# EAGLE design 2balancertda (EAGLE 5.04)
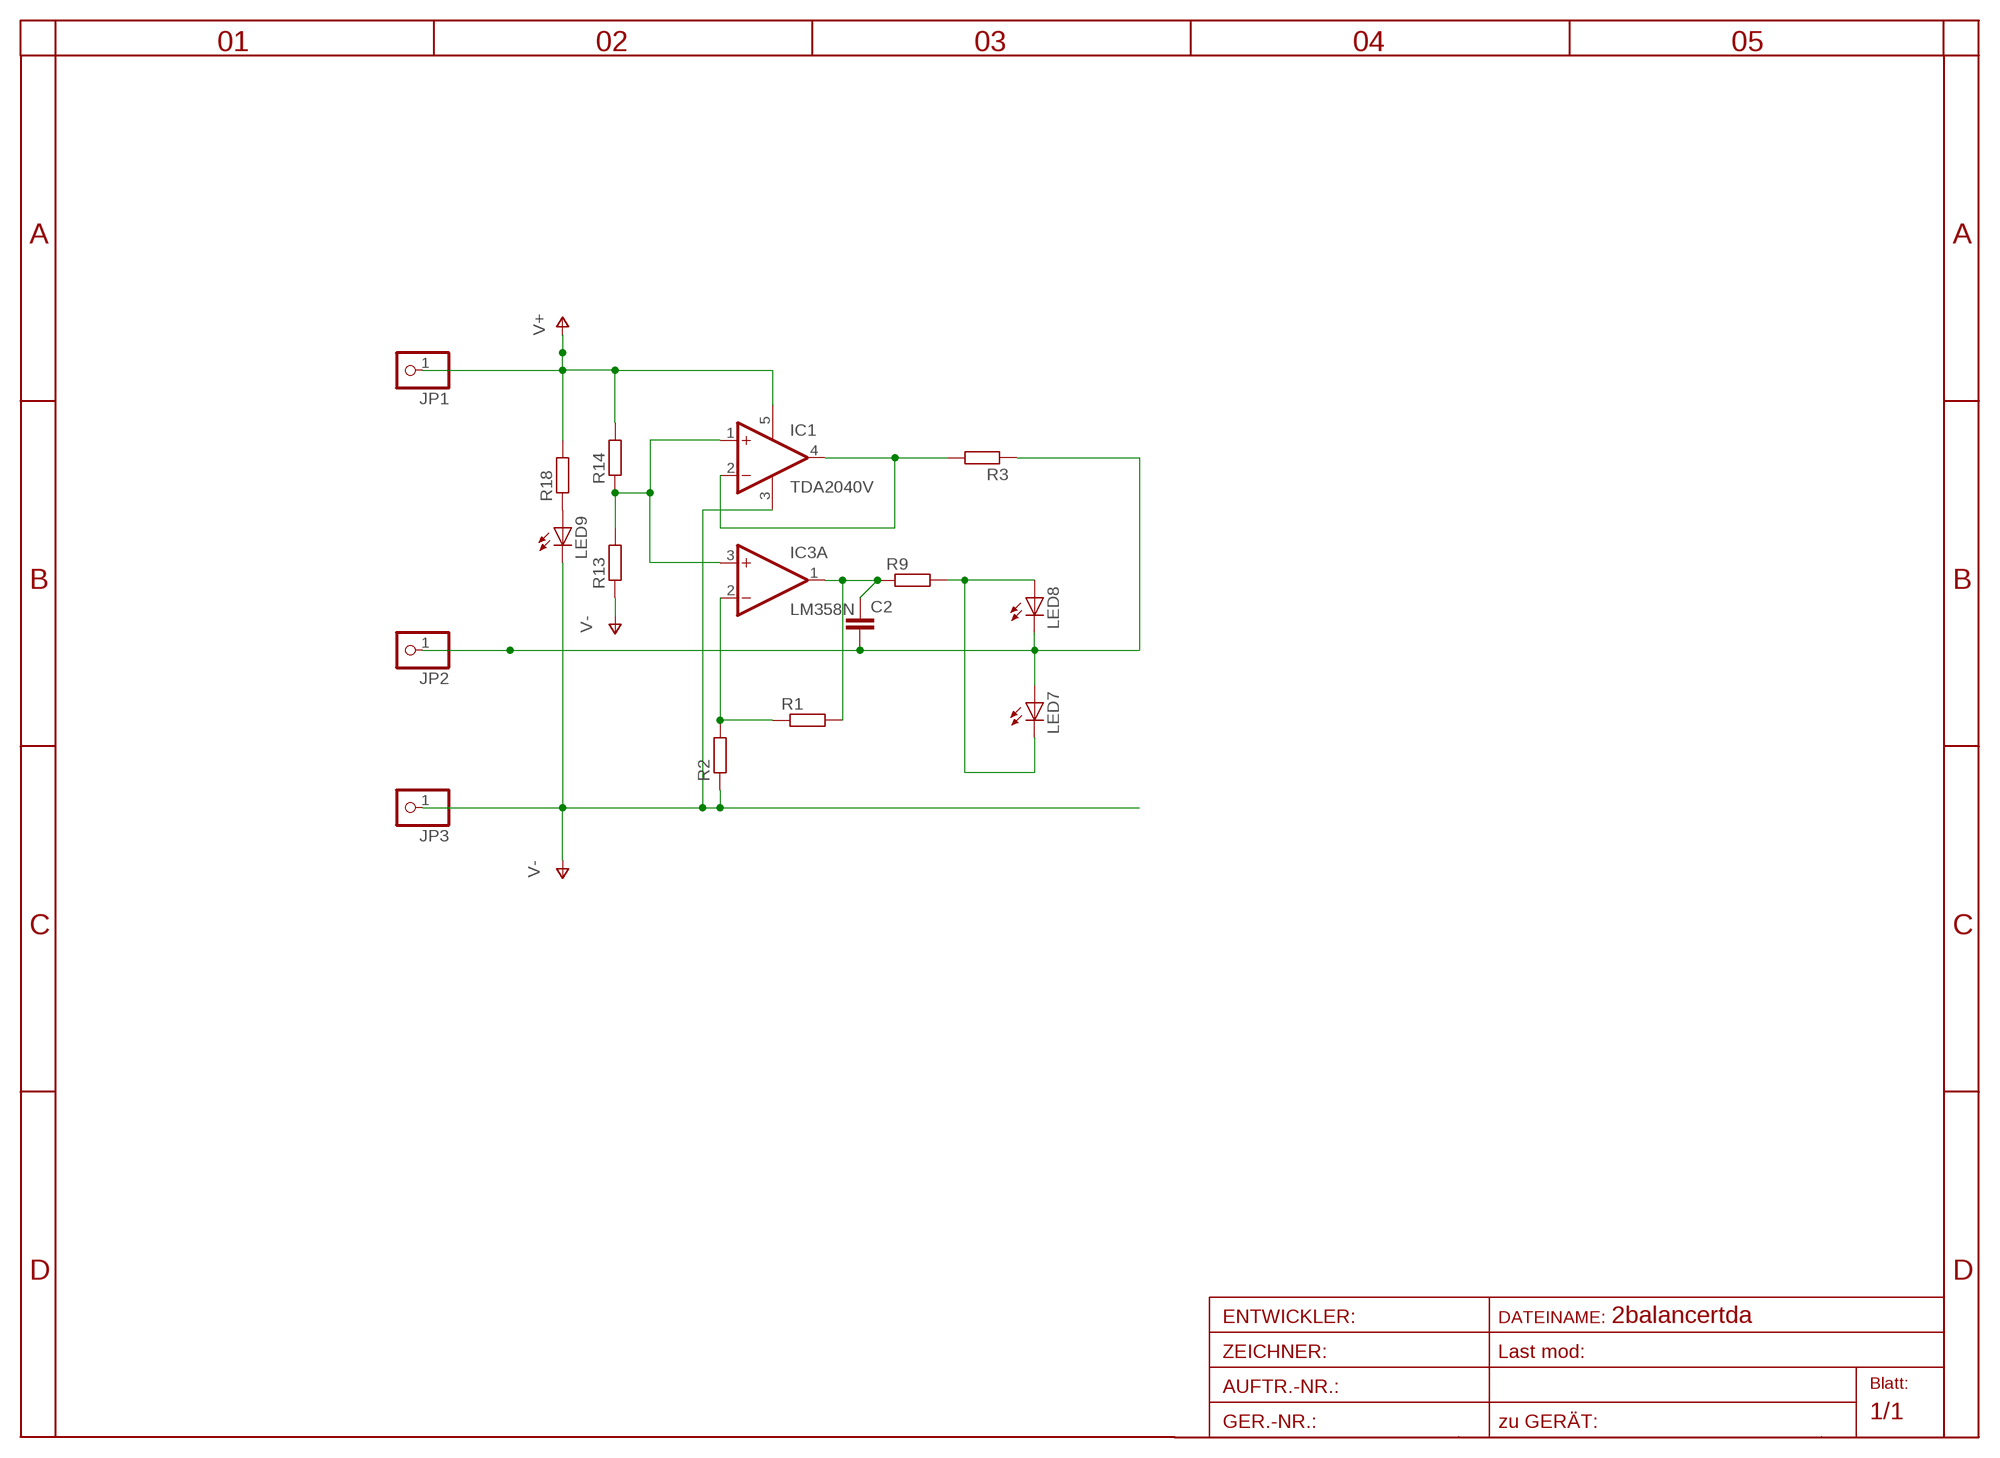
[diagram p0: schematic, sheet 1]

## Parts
C2  C-EU025-024X044  [C025-024X044]
IC1  TDA2040V  [CB360]
IC3  LM358N  [DIL08]
JP1  PINHD-1X1  [1X01]
JP2  PINHD-1X1  [1X01]
JP3  PINHD-1X1  [1X01]
LED7  LED3MM  [LED3MM]
LED8  LED3MM  [LED3MM]
LED9  LED3MM  [LED3MM]
R1  R-EU_0204/5  [0204/5]
R2  R-EU_0204/5  [0204/5]
R3  R-EU_0613/15  [P0613/15]
R9  R-EU_0204/5  [0204/5]
R13  R-EU_0204/5  [0204/5]
R14  R-EU_0204/5  [0204/5]
R18  R-EU_0204/5  [0204/5]

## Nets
B1: C2.2 JP2.1 LED7.A LED8.K(C) R3.1
N$1: IC3.2(A:-IN) R1.1 R2.2
N$2: IC1.2(-IN) IC1.4(OUT) R3.2
N$9: LED7.K(C) LED8.A R9.2
N$25: C2.1 IC3.1(A:OUT) R1.2 R9.1
N$28: IC1.1(+IN) IC3.3(A:+IN) R13.2 R14.1
N$34: LED9.A R18.1
V+: IC1.5(V+) JP1.1 R14.2 R18.2
V-: IC1.3(V-) JP3.1 LED9.K(C) R2.1 R13.1
Unconnected: IC3.5(B:+IN) IC3.6(B:-IN) IC3.7(B:OUT)

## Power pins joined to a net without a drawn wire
V+: IC3.8(P:V+)
V-: IC3.4(P:V-)

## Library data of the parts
C2 = rcl-2:C-EU: CAPACITOR, European symbol
IC1 = linear:TDA2040: Power OP AMP
IC3 = linear:LM358: OP AMP also LM158; LM258; LM2904 Source: http://cache.national.com/ds/LM/LM158.pdf
JP1-JP3 = pinhead:PINHD-1X1: PIN HEADER
LED7-LED9 = led:LED: LED
R1-R3 R9 R13 R14 R18 = rcl-2:R-EU_: RESISTOR, European symbol

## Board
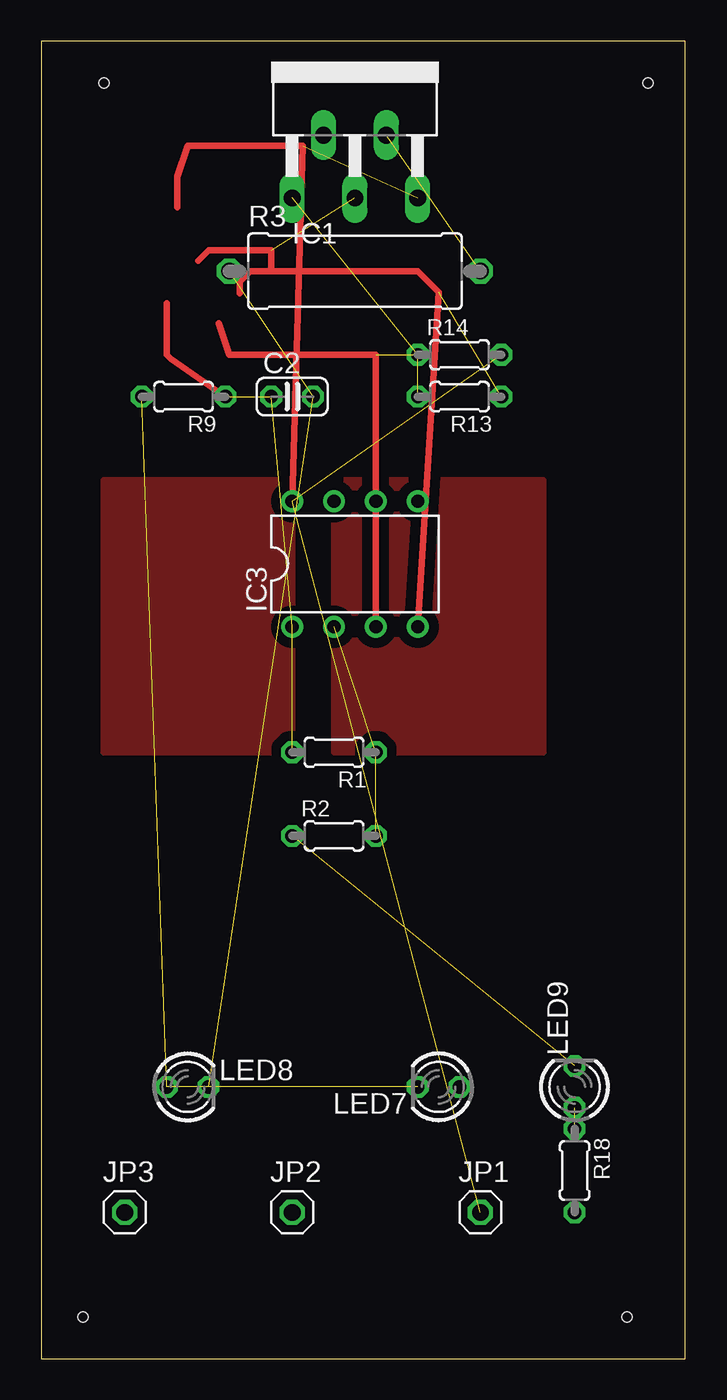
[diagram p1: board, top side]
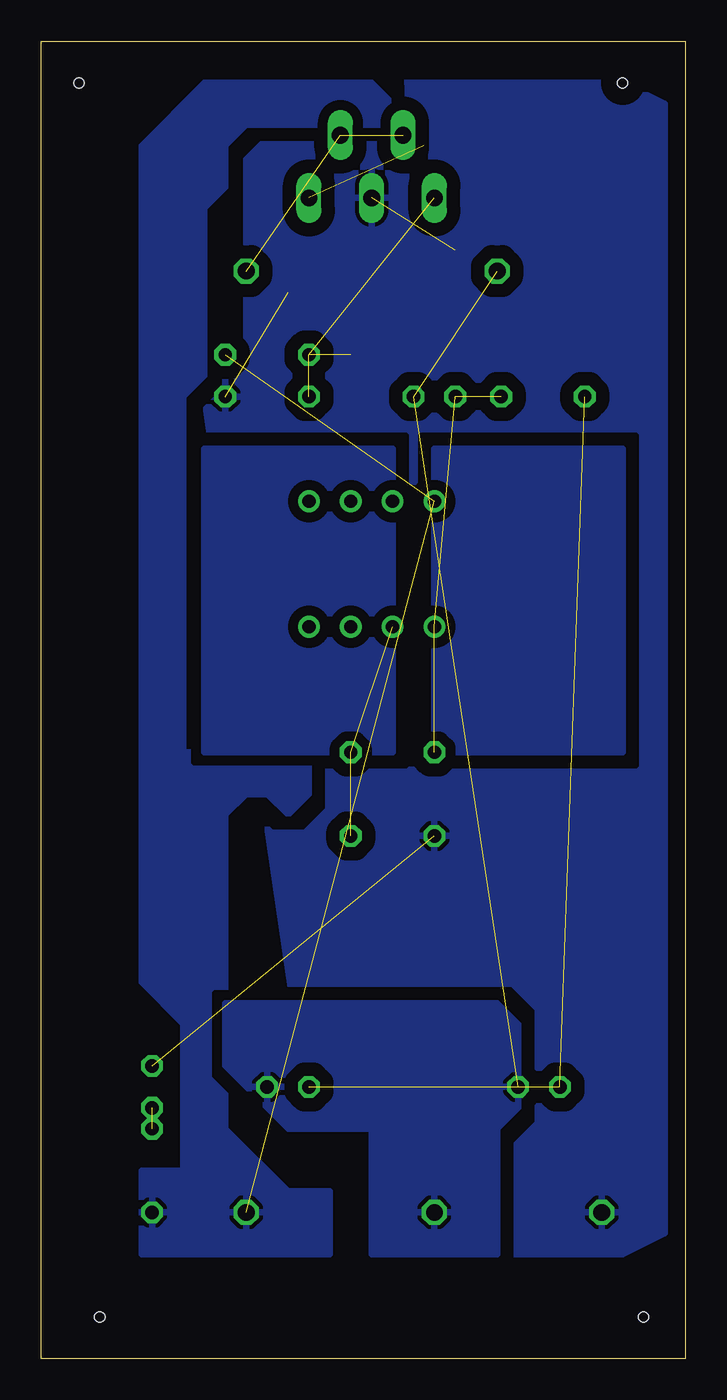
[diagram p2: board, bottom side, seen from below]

Size 39.12 x 80 mm. Coordinates in mm from the lower left corner, seen from the top.
Outline: 0,0 39.12,0 39.12,80 0,80 0,0
Copper layers (1*16): Top 0.035mm / dielectric 1.5mm / Bottom 0.035mm
Design rules "default": minimum track width 10mil, minimum drill 24mil, track to track 8mil, track to pad 8mil, pad to pad 8mil, via to via 8mil, smd to smd 8mil, copper to edge 40mil, drill to drill 8mil, minimum pad ring 10mil, minimum via ring 8mil, stop-mask expansion 4mil, vias tented up to drill 0mil, thermal gap 10mil
Holes 0.6 mm at 2.54,2.54 35.56,2.54 36.83,77.47 3.81,77.47

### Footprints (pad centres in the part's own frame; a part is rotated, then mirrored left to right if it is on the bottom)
C025-024X044 = drill 0.813 octagon: 1 -1.27,0; 2 1.27,0
CB360 = drill 1.016 long: 1 -3.81,-8.255; 2 -1.905,-4.445; 3 0,-8.255; 4 1.905,-4.445; 5 3.81,-8.255
DIL08 = drill 0.813 pad 1.27 round: 1 -3.81,-3.81; 2 -1.27,-3.81; 3 1.27,-3.81; 4 3.81,-3.81; 5 3.81,3.81; 6 1.27,3.81; 7 -1.27,3.81; 8 -3.81,3.81
1X01 = drill 1.016 octagon: 1 0,0
LED3MM = drill 0.813 octagon: A -1.27,0; K 1.27,0
0204/5 = drill 0.813 octagon: 1 -2.54,0; 2 2.54,0
P0613/15 = drill 1.016 octagon: 1 -7.62,0; 2 7.62,0

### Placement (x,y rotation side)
C2  15.24,58.42 0 top
IC1  19.05,78.74 0 top
IC3  19.05,48.26 0 top
JP1  26.67,8.89 0 top
JP2  15.24,8.89 0 top
JP3  5.08,8.89 0 top
LED7  24.13,16.51 180 top
LED8  8.89,16.51 0 top
LED9  32.38,16.51 90 top
R1  17.78,36.83 180 top
R2  17.78,31.75 0 top
R3  19.05,66.04 0 top
R9  8.65,58.42 180 top
R13  25.4,58.42 180 top
R14  25.4,60.96 0 top
R18  32.38,11.43 270 top

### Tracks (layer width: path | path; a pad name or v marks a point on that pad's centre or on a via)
B1  (2 unrouted)
  pour Bottom (isolate 0.813, rank 3): 11.43,6.35 11.43,13.97 10.16,15.24 10.16,20.32 11.43,21.59 27.94,21.59 27.94,17.78 24.13,13.97 19.05,13.97 19.05,6.35
N$1  (2 unrouted)
N$2  (2 unrouted)
N$9  (2 unrouted)
N$25  (3 unrouted)
  Top 0.406: R9.1 7.86,60.72 7.62,60.96 7.62,64.08
N$28  (3 unrouted)
  Top 0.406: 10.79,62.87 11.43,60.96 20.32,60.96 IC3.3
N$31
  pour Top (isolate 0.61, rank 4): 3.81,53.34 15.24,53.34 15.24,36.83 3.81,36.83
  pour Top (isolate 0.61, rank 4): 17.78,53.34 30.48,53.34 30.48,36.83 17.78,36.83
  pour Bottom (isolate 0.61, rank 4): 3.81,55.24 15.24,55.24 15.24,36.83 3.81,36.83
  pour Bottom (isolate 0.61, rank 3): 17.78,55.24 29.21,55.24 29.21,36.83 17.78,36.83
N$34  (1 unrouted)
V+  (3 unrouted)
  Top 0.406: 8.26,69.91 8.26,71.75 8.89,73.66 15.88,73.66 IC3.8
  pour Bottom (isolate 0.61, rank 4): 30.48,11.43 33.02,11.43 33.02,6.35 21.59,6.35 21.59,10.16 24.13,10.16 27.94,13.97 27.94,33.02 26.67,34.29 25.4,34.29 24.13,33.02 22.86,34.29 22.86,36.83 30.48,36.83 30.48,58.42 29.21,59.69 29.21,69.85 27.94,71.12 27.94,73.66 26.67,74.93 17.78,74.93 17.78,76.2 19.05,77.47 29.21,77.47 33.02,73.66 33.02,22.86 30.48,20.32
V-  (3 unrouted)
  Top 0.406: 9.53,66.67 10.16,67.31 13.97,67.31 13.97,66.04 | 12.06,64.71 12.06,65.41 12.7,66.04 13.97,66.04 | 13.97,66.04 22.86,66.04 24.13,64.77 IC3.4
  pour Bottom (isolate 0.813, rank 5): 21.59,6.35 3.81,6.35 1.27,7.62 1.27,76.2 3.81,77.47 24.13,77.47 26.67,74.93 26.67,60.96 29.21,58.42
